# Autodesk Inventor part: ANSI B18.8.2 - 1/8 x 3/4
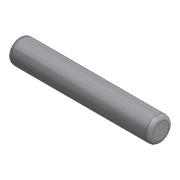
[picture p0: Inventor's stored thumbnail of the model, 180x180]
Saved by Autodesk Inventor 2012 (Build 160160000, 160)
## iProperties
Created: 2000-07
Part Number: ANSI B18.8.2 - 1/8 x 3/4
Material: Stainless Steel, Austenitic
Description: Pin - Hardened  Dowel 1/8 x 3/4
Document SubType Name: Standard Catalog Part
Standard: ANSI B18.8.2 - 1/8 x 3/4
Designer: Ron
Mass: 1.20288 g
Surface Area: 2.01271 cm^2
Volume: 0.149799 cm^3
Density: 8.03 g/cm^3
Control State: 0
Master: False
Checked Out: False
Shininess: 60.0
Length Units: 11272
Angle Units: 11279
Time Units: 11290
Mass Units: 11286
Length Display Precision: 3
Angle Display Precision: 2
Density: 0.0
Volumn: 0.0
Area: 0.0
PropertySet Name: Model Information
Author: Ron
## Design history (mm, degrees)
node "Base1"
body "Solid1"
